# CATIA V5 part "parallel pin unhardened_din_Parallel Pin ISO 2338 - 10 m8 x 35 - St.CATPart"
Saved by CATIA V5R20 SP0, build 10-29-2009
Part number: parallel pin unhardened_din_Parallel Pin ISO 2338 - 10 m8 x 35 - St
Revision: ANY
Definition: UNKNOWN
Nomenclature: parallel pin unhardened_din_Parallel Pin ISO 2338 - 10 m8 x 35 - St
Source: Unknown
Bounding box of the stored display mesh (mm): x 0 to 35, y -5 to 5, z -5 to 5
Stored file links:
  C:\Users\Utente\Desktop\IO LAVORO\3D X SITO CF\CUMSA\3D files SL.602008\SL 602008\parallel pin unhardened_din_Parallel Pin ISO 2338 - 10 m8 x 35 - St.CATPart
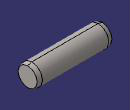
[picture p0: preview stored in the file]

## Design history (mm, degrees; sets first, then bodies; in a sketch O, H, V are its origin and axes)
Body1 "Base-Revolve" (main body)
  Solid1: solid without history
